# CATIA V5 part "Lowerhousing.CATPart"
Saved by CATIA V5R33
Part number: Lowerhousing
Bounding box of the stored display mesh (mm): x -75 to 75, y -40 to 40, z -68 to -0.1
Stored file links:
  D:\PROJECTS\Project 2023\CATIA V5 6R 2023\Resources\Tutorial Files\c12_catia_v5_6r2023_tut\c12Tut1\Lowerhousing.CATPart
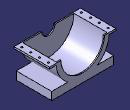
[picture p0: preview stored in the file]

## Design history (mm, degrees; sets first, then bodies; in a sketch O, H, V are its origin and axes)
Body1 (main body)
  Sketch1 on zx-plane, origin (0, 0, 0), H (-1, 0, 0), V (0, 0, 1)
    line L1 (-75, -0.1) -> (75, -0.1)
    point P1 (-75, -0.1)
    arc A1 centre (0, 0) radius 60 from (-59.8598, -4.1) to (-33.1662, -50) ccw
    line L2 (-75, -4.1) -> (-59.8598, -4.1)
    line L3 (-70, -68) -> (70, -68)
    point P6 (70, -68)
    line L4 (-70, -50) -> (-33.1662, -50)
    line L5 (70, -68) -> (70, -50)
    line L6 (-70, -68) -> (-70, -50)
    arc A2 centre (0, 0) radius 60 from (33.1662, -50) to (59.8598, -4.1) ccw
    point P10 (33.1662, -50)
    line L7 (33.1662, -50) -> (70, -50)
    line L8 (75, -4.1) -> (75, -0.1)
    line L9 (-75, -4.1) -> (-75, -0.1)
    point P11 (59.8598, -4.1)
    line L10 (59.8598, -4.1) -> (75, -4.1)
    length L1 = 150
    distance P1 V = 75
    distance L2 L1 = 4
    distance L3 H = 68
    distance L4 L3 = 18
    distance P6 V = 70
    length L3 = 140
    radius A1 = 60
    horizontal: L1 H, L2 H, L3 H, L4 H, L7 H, L10 H
    vertical: L6 V, L5 V, L8 V, L9 V
    coincidence: L4 P10, A1 A2, L4 L7, L2 P11, L2 L10
  Pad1: profile Sketch1, direction (0, 1, 0), length 40, mirrored extent
  Sketch2 on face of Pad1, origin (0, 0, -0.1), H (1, 0, 0), V (0, 1, 0)
    circle A1 centre (-67.5, 30) radius 2
    point P1 (-67.5, 30)
    reference projected line E1 (-75, 40) -> (75, 40) from edge of Pad1
    reference projected line E2 (-75, -40) -> (-75, 40) from edge of Pad1
    radius A1 = 2
    distance E1 P1 = 10
    distance E2 P1 = 7.5
  Pocket1: profile Sketch2, direction (0, 0, -1), through (limit type 6)
  RectPattern1: of Pocket1, direction 1 instances 4, spacing 20, along edge of Pad1 reversed, direction 2 instances 2, spacing 135, along edge of Pad1 reversed
  Sketch3 on face of Pad1, origin (0, 0, -0.1), H (1, 0, 0), V (0, 1, 0)
    point P1 (0, -37.5)
    line L1 (0, -37.5) -> (57.5, -37.5)
    line L2 (57.5, -37.5) -> (57.5, 37.5)
    line L3 (57.5, 37.5) -> (0, 37.5)
    line L4 (0, 37.5) -> (0, -37.5)
    reference projected line E1 (-75, 40) -> (75, 40) from edge [face of Pad1 from Sketch1.L1 | end face of Pad1]
    reference projected line E2 (-75, -40) -> (75, -40) from edge [start face of Pad1 | face of Pad1 from Sketch1.L1]
    length L3 = 57.5
    distance L3 E1 = 2.5
    distance L1 E2 = 2.5
    coincidence: P1 V
    horizontal: L1 H, L3 H
    vertical: L2 V, L4 V
  Groove1: profile Sketch3, axis edge of Sketch3, angle 360
  Sketch4 on face of Pad1, origin (0, 40, 0), H (-1, 0, 0), V (0, 0, 1)
    circle A1 centre (0, 0) radius 15
    circle A2 centre (0, 0) radius 49
    radius A2 = 49
    radius A1 = 15
  MultiPocket1: profile Sketch4, domains (length 25.4; length 279.4)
